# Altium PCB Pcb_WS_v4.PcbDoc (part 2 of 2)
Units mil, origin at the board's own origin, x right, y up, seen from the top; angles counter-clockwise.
Board outline 3890 x 3890 mil, 2 copper layers (Top Layer, Bottom Layer); 77 components, 63 nets, 250 pads, 399 vias.
Unrouted connection lines stored in the file: 3.
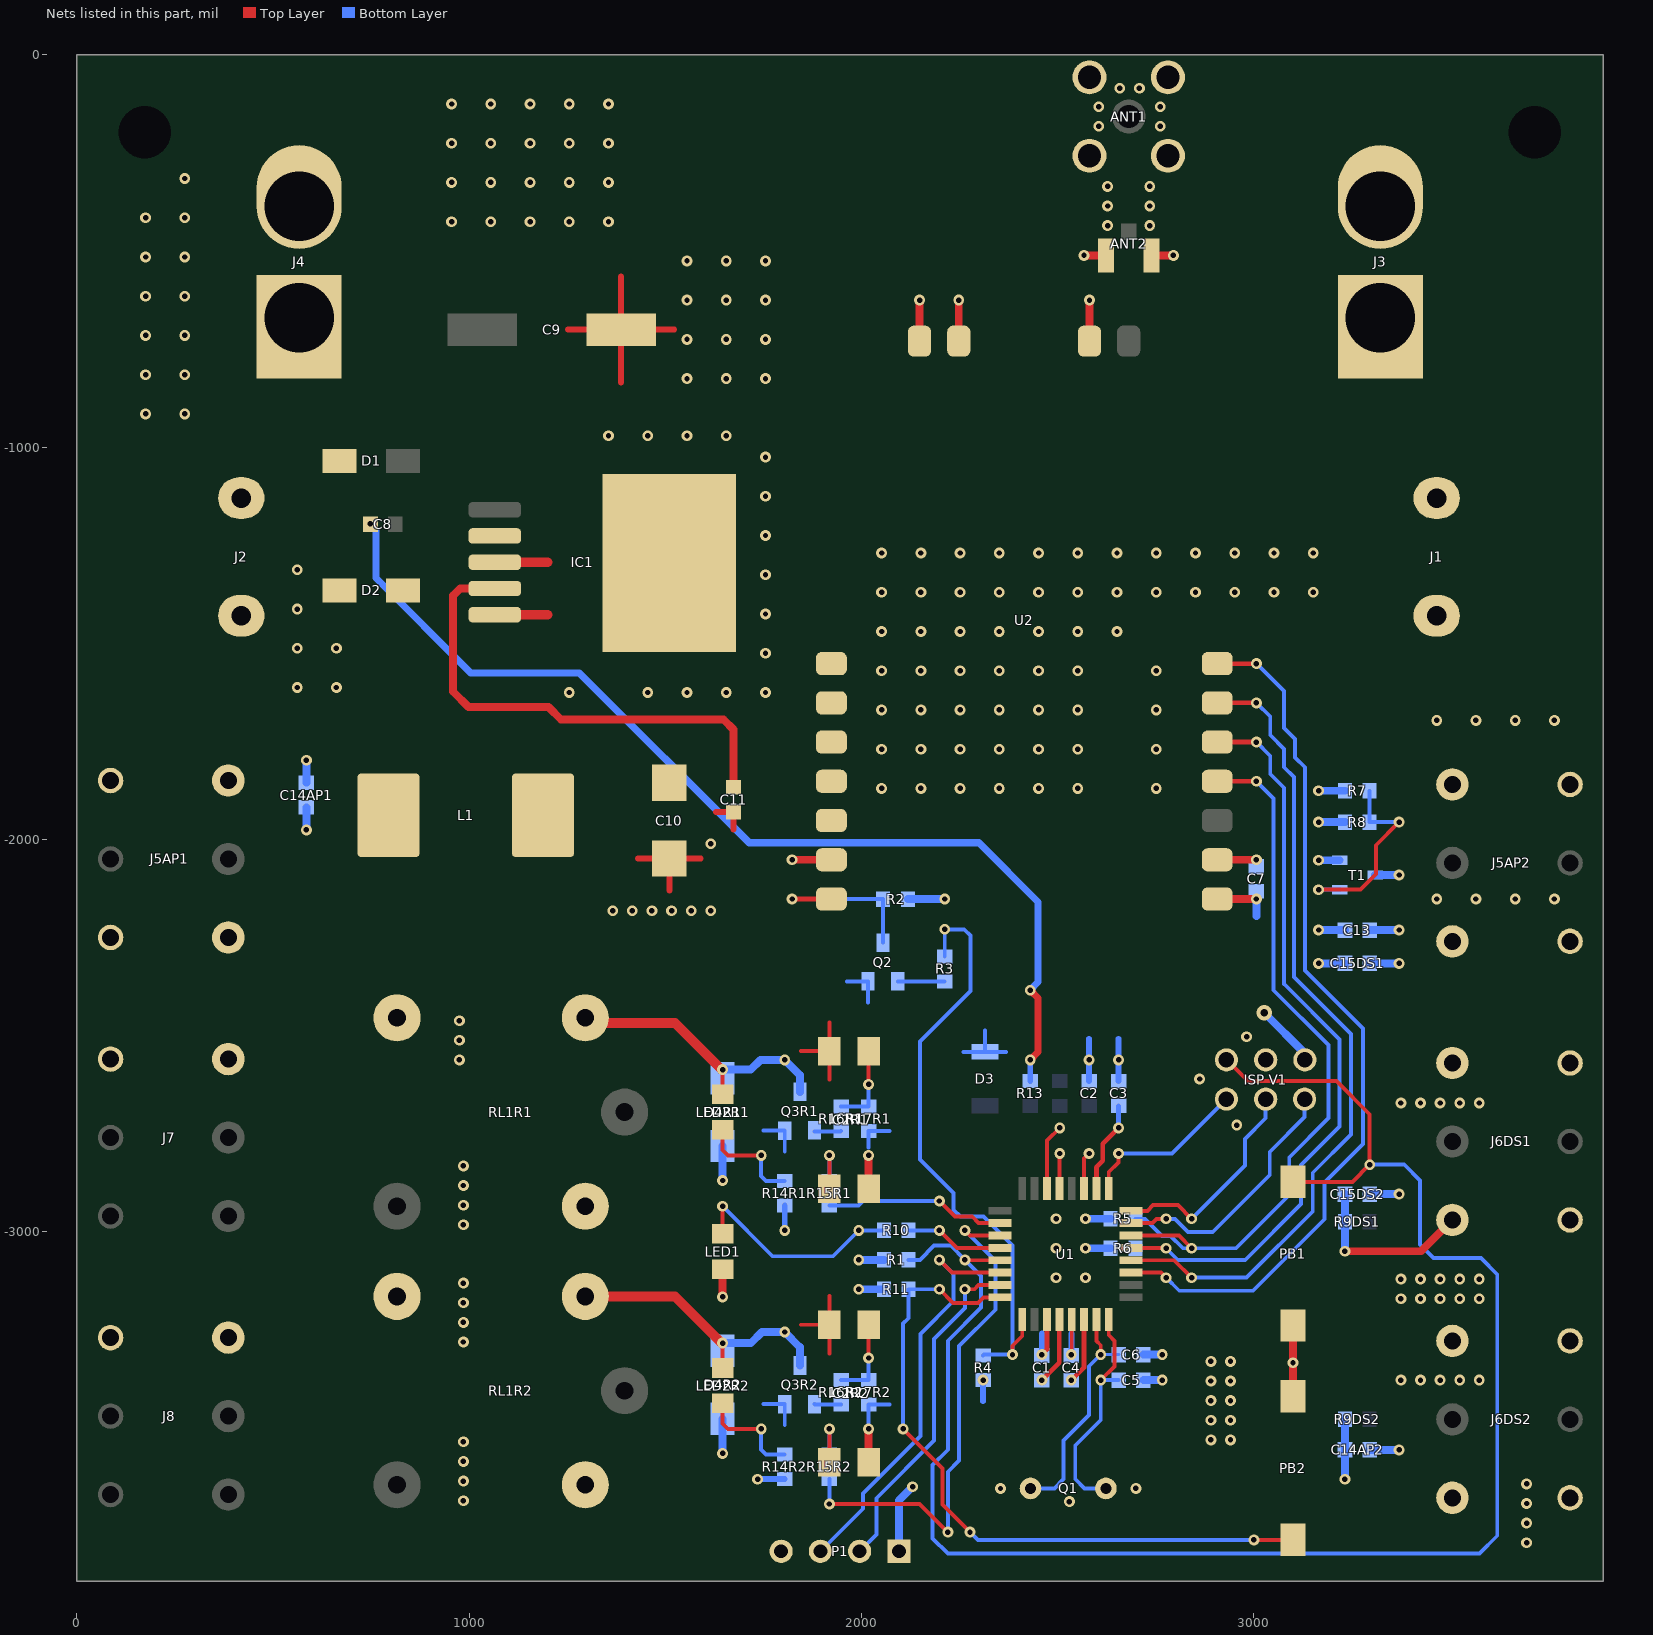
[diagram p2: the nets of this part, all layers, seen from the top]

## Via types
v1: diameter 27.56, hole 13.78, Top Layer to Bottom Layer, tented both sides, 320 vias
v2: diameter 20, hole 11.81, Top Layer to Bottom Layer, tented both sides, 76 vias
v3: diameter 27.56, hole 13.78, Top Layer to Bottom Layer, tented top, 2 vias
v4: diameter 39.37, hole 19.68, Top Layer to Bottom Layer, tented both sides, 1 vias

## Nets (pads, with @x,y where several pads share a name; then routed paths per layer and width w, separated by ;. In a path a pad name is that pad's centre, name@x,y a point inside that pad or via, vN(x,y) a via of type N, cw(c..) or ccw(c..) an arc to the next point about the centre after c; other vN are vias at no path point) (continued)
GND: "ISP V1.5" C1.2 C2.1 C3.2 C4.2 C5.2 C6.2 C7.2 C8.2 C9.2 C10.2 C11.2 C13.2 C14AP1.1 C14AP2.1 C15DS1.1 C15DS2.1 D2.2 D3.2 IC1.3 IC1.5 IC1.6 IC2R1.2 IC2R2.2 J2.1 J4.1 J5AP1.3 J5AP2.3 J6DS1.3 J6DS2.3 LED1.2 P1.4 PB1.2 PB2.2 Q2.2 Q3R1.2 Q3R2.2 R4.1 R5.2 R6.2 R7.1 R13.2 R17R1.1 R17R2.1 U1.3 U1.5 U1.21 U2.7 U2.9 | length 6440.5
  Top Layer w9.84: U1.21@2504.06,-2889.41 2504.06,-2800.94 v1(2505,-2800) ; v1(2534.61,-3312.82) 2535.55,-3311.87 U1.5@2535.55,-3223.41
  Top Layer w12: v1(2459.61,-3312.82) 2472.56,-3299.87 U1.3@2472.56,-3223.41
  Top Layer w15: 1251.94,-700 C9.2@1387.17,-700 ; 1387.17,-835.23 C9.2@1387.17,-700 ; 1387.17,-564.77 C9.2@1387.17,-700 ; 1430,-2047.96 C10.2@1510,-2047.96 1590,-2047.96 ; 1510.45,-2130.07 C10.2@1510.45,-2050.07 ; 1522.4,-700 C9.2@1387.17,-700 ; 1629.05,-1929.5 C11.2@1673.55,-1929.5 1673.55,-1974
  Top Layer w18: v1(2430,-2561.61) 2450,-2541.61 2450,-2512.31 2450,-2404 v1(2430,-2384)
  Top Layer w20: v1(1645.86,-3165.54) LED1.2@1645.86,-3095 ; v1(1822.96,-2051.51) U2.9@1922.96,-2051.51 ; IC2R2.2@2017.86,-3586.94 v1(2017.86,-3502.13) ; IC2R1.2@2017.86,-2889.66 v1(2017.86,-2804.85) ; U2.7@2906.43,-2151.51 v3(3006.43,-2151.51) ; PB2.2@3099.53,-3418.86 v1(3099.53,-3333.37) PB1.2@3099.53,-3238.46
  Top Layer w25: IC1.5@1065.04,-1426.9 1200.27,-1426.9 ; IC1.3@1065.04,-1293.04 1200.27,-1293.04
  Bottom Layer w10: 1750.16,-3438.9 Q3R2.2@1804.06,-3438.9 1804.06,-3492.8 ; 1750.16,-2741.62 Q3R1.2@1804.06,-2741.62 1804.06,-2795.52 ; 1962.5,-2361.42 Q2.2@2016.4,-2361.42 2016.4,-2415.32 ; v1(2017.86,-3502.13) R17R2.1@2017.86,-3440.26 2071.76,-3440.26 ; 2017.86,-2784.35 R17R1.1@2017.86,-2742.98 2071.76,-2742.98 ; 2260.17,-2540.88 D3.2@2314.07,-2540.88 ; 2314.07,-2486.98 D3.2@2314.07,-2540.88 ; 2367.98,-2540.88 D3.2@2314.07,-2540.88
  Bottom Layer w15: 2309.61,-3431.72 v1(2309.61,-3377.82) ; R13.2@2430,-2615.69 v1(2430,-2561.61) ; v1(2459.61,-3312.82) 2459.61,-3258.92 ; v1(2534.61,-3312.82) 2534.61,-3258.92 ; C2.1@2580,-2615.69 v1(2580,-2561.61) 2580,-2507.53 ; C3.2@2655,-2615.69 v1(2655,-2561.61) 2655,-2507.53
  Bottom Layer w18: v1(748,-1195.22) 748,-1196.54 762,-1210.54 762,-1333.26 1003.74,-1575 1280.5,-1575 1713.5,-2008 2299.34,-2008 2450,-2158.67 2450,-2363.3 2430,-2383.3 v1(2430,-2384)
  Bottom Layer w20: C14AP1.1@585,-1855 v1(585,-1797.68) ; v1(2570.81,-3041.61) R6.2@2634.67,-3041.61 ; v1(2570.81,-2966.61) R5.2@2634.67,-2966.61 ; C5.2@2718.3,-3377.82 v1(2766.21,-3377.82) ; C6.2@2718.3,-3312.82 v1(2766.21,-3312.82) ; 3006.43,-2195 v3(3006.43,-2151.51) ; v1(3165,-2315.54) C15DS1.1@3232.01,-2315.54 ; v1(3165,-2230.54) C13.2@3232.01,-2230.54 ; v1(3165,-1875.54) R7.1@3232.01,-1875.54 ; C14AP2.1@3295,-3555.54 v1(3370,-3555.54) ; C15DS2.1@3295,-2903.69 v1(3370,-2903.69)
  other v1: 2529.75,-3687.48 985,-3685 2353.96,-3654.09 2699.14,-3653.67 985,-3635 985,-3585 985,-3535 2890.32,-3529.98 2940.32,-3529.98 2890.32,-3479.98 2940.32,-3479.98 2890.32,-3429.98 2940.32,-3429.98 2890.32,-3379.98 2940.32,-3379.98 3374.51,-3377.82 3424.51,-3377.82 3474.51,-3377.82 3524.51,-3377.82 3574.51,-3377.82 2890.32,-3329.98 2940.32,-3329.98 985,-3280.49 985,-3230.49 985,-3180.49 3374.51,-3170.39 3424.51,-3170.39 3474.51,-3170.39 3524.51,-3170.39 3574.51,-3170.39 985,-3130.49 3374.51,-3120.39 3424.51,-3120.39 3474.51,-3120.39 3524.51,-3120.39 3574.51,-3120.39 2495.81,-3116.61 2570.81,-3116.61 2495.81,-3041.61 985,-2981.79 2495.81,-2966.61 985,-2931.79 985,-2881.79 985,-2831.79 2956.35,-2727.67 3374.51,-2671.35 3424.51,-2671.35 3474.51,-2671.35 3524.51,-2671.35 3574.51,-2671.35 2861.6,-2610.31 975,-2561.61 975,-2511.61 2981.3,-2502.57 975,-2461.61 1365.62,-2181.28 1415.62,-2181.28 1465.62,-2181.28 1515.62,-2181.28 1565.62,-2181.28 1615.62,-2181.28 3465.86,-2151.51 3565.86,-2151.51 3665.86,-2151.51 3765.86,-2151.51 1615.62,-2010.75 2051.06,-1869.52 2151.06,-1869.52 2251.06,-1869.52 2351.06,-1869.52 2451.06,-1869.52 2551.06,-1869.52 2751.06,-1869.52 2051.06,-1769.52 2151.06,-1769.52 2251.06,-1769.52 2351.06,-1769.52 2451.06,-1769.52 2551.06,-1769.52 2751.06,-1769.52 3465.86,-1696.29 3565.86,-1696.29 3665.86,-1696.29 3765.86,-1696.29 2051.06,-1669.52 2151.06,-1669.52 2251.06,-1669.52 2351.06,-1669.52 2451.06,-1669.52 2551.06,-1669.52 2751.06,-1669.52 1255,-1625 1455,-1625 1555,-1625 1655,-1625 1755,-1625 561.41,-1612.43 661.41,-1612.43 2051.06,-1569.52 2151.06,-1569.52 2251.06,-1569.52 2351.06,-1569.52 2451.06,-1569.52 2551.06,-1569.52 2751.06,-1569.52 1755,-1525 561.41,-1512.43 661.41,-1512.43 2051.06,-1469.52 2151.06,-1469.52 2251.06,-1469.52 2351.06,-1469.52 2451.06,-1469.52 2551.06,-1469.52 2651.06,-1469.52 1755,-1425 561.41,-1412.43 2051.06,-1369.52 2151.06,-1369.52 2251.06,-1369.52 2351.06,-1369.52 2451.06,-1369.52 2551.06,-1369.52 2651.06,-1369.52 2751.06,-1369.52 2851.06,-1369.52 2951.06,-1369.52 3051.06,-1369.52 3151.06,-1369.52 1755,-1325 561.41,-1312.43 2051.06,-1269.52 2151.06,-1269.52 2251.06,-1269.52 2351.06,-1269.52 2451.06,-1269.52 2551.06,-1269.52 2651.06,-1269.52 2751.06,-1269.52 2851.06,-1269.52 2951.06,-1269.52 3051.06,-1269.52 3151.06,-1269.52 1755,-1225 1755,-1125 1755,-1025 1355,-970.49 1455,-970.49 1555,-970.49 1655,-970.49 175,-915 275,-915 1555,-825 1655,-825 1755,-825 175,-815 275,-815 1555,-725 1655,-725 1755,-725 175,-715 275,-715 1555,-625 1655,-625 1755,-625 175,-615 275,-615 1555,-525 1655,-525 1755,-525 175,-515 275,-515 955,-425 1055,-425 1155,-425 1255,-425 1355,-425 175,-415 275,-415 955,-325 1055,-325 1155,-325 1255,-325 1355,-325 275,-315 955,-225 1055,-225 1155,-225 1255,-225 1355,-225 955,-125 1055,-125 1155,-125 1255,-125 1355,-125
GND-SOLAR: J1.2 J3.1
GND_ANT: ANT1.2 ANT2.2 U2.15 U2.16 U2.17 | length 425.1
  Top Layer w20: U2.15@2147.76,-729.46 v1(2147.76,-625) ; U2.16@2247.76,-729.46 v1(2247.76,-625) ; v1(2566.92,-511) ANT2.2@2622.76,-511 ; U2.17@2580.84,-729.46 v1(2580.84,-625) ; ANT2.2@2738.91,-511 v1(2794.75,-511)
  other v1: 2627.07,-435 2734.27,-435 2627.07,-385 2734.27,-385 2627.07,-335 2734.27,-335 2604.38,-181.91 2761.22,-181.91 2604.38,-131.91 2761.22,-131.91 2658.24,-85.19 2708.24,-85.19
LED: R10.1 U1.28 | length 251.5
  Top Layer w10: v1(2198.39,-2996.21) 2242.84,-3040.66 U1.28@2352.8,-3040.66
  Bottom Layer w10: R10.1@2119.71,-2996.21 v1(2198.39,-2996.21)
M0: U1.11 U2.1 | length 2257
  Top Layer w10: U1.11@2686.8,-3103.65 2763.26,-3103.65 v1(2776.21,-3116.61)
  Top Layer w12: U2.1@2906.43,-1551.51 v1(3006.43,-1551.51)
  Bottom Layer w10: v1(2776.21,-3116.61) 2809.61,-3150 2997.76,-3150 3180,-2967.76 3180,-2873.56 3277.78,-2775.78 3277.78,-2481.78 3130,-2334 3130,-1815.68 3104.99,-1790.67 3104.99,-1743.7 3076.66,-1715.38 3076.66,-1621.74 v1(3006.43,-1551.51)
M1: U1.12 U2.2 | length 2088.2
  Top Layer w10: U1.12@2686.8,-3072.16 2796.76,-3072.16 v1(2841.21,-3116.61)
  Top Layer w12: U2.2@2906.43,-1651.51 v1(3006.43,-1651.51)
  Bottom Layer w10: v1(2841.21,-3116.61) 2981.3,-3116.61 3150,-2947.91 3150,-2849.22 3247.63,-2751.6 3247.63,-2495.7 3101.84,-2349.92 3101.84,-1840.85 3076.66,-1815.68 3076.66,-1768.71 3041.54,-1733.59 3041.54,-1686.63 v1(3006.43,-1651.51)
MISO: "ISP V1.2" U1.16 | length 558.1
  Top Layer w10: U1.16@2686.8,-2946.17 2728.65,-2946.17 2743.21,-2931.61 2806.21,-2931.61 v1(2841.21,-2966.61)
  Bottom Layer w10: v1(2841.21,-2966.61) 2976.74,-2831.08 2976.74,-2763.58 3030,-2710.32 3030,-2661.61
MOSI: "ISP V1.3" U1.15 | length 662
  Top Layer w10: U1.15@2686.8,-2977.67 2741.13,-2977.67 2752.19,-2966.61 v1(2776.21,-2966.61)
  Bottom Layer w10: v1(2776.21,-2966.61) 2798.31,-2966.61 2831.71,-3000 2895.12,-3000 3040.32,-2854.81 3040.32,-2795.88 3129,-2707.19 3129,-2661.61
NetD2_1: D2.1 IC1.2 L1.1
NetD4R1_2: D4R1.2 LED2R1.2 Q3R1.3 RL1R1.4 | length 728.5
  Top Layer w10: LED2R1.2@1645.86,-2649.46 v1(1645.86,-2586.19)
  Top Layer w25: RL1R1.4@1295.86,-2467.18 1524.46,-2467.18 v1@1643.47,-2586.19
  Bottom Layer w20: D4R1.2@1643.47,-2586.19 v1(1645.86,-2586.19) 1717.53,-2586.19 1742.12,-2561.61 v1(1804.06,-2561.61) 1842.66,-2600.2 Q3R1.3@1842.66,-2643.2
NetD4R2_2: D4R2.2 LED2R2.2 Q3R2.3 RL1R2.4 | length 734
  Top Layer w10: LED2R2.2@1645.86,-3346.74 v1(1645.86,-3283.47)
  Top Layer w25: RL1R2.4@1295.86,-3164.46 1524.46,-3164.46 v1@1643.47,-3283.47
  Bottom Layer w20: D4R2.2@1643.47,-3283.47 1717.53,-3283.47 1746,-3255 v1(1804.06,-3255) 1842.66,-3293.6 Q3R2.3@1842.66,-3340.48
NetIC2R1_1: IC2R1.1 R15R1.2 | length 149.9
  Top Layer w10: IC2R1.1@1917.86,-2889.66 v1(1917.86,-2804.85)
  Bottom Layer w10: R15R1.2@1917.86,-2869.99 v1(1917.86,-2804.85)
NetIC2R2_1: IC2R2.1 R15R2.2 | length 149.9
  Top Layer w10: IC2R2.1@1917.86,-3586.94 v1(1917.86,-3502.13)
  Bottom Layer w10: R15R2.2@1917.86,-3567.27 v1(1917.86,-3502.13)
NetLED1_1: LED1.1 R10.2 | length 561.5
  Top Layer w10: LED1.1@1645.86,-3005 v1(1645.86,-2934.46)
  Bottom Layer w10: v1(1645.86,-2934.46) 1773.4,-3062 1927.07,-3062 v1(1992.86,-2996.21) R10.2@2056.72,-2996.21
NetLED2R1_1: LED2R1.1 R14R1.2 | length 273.2
  Top Layer w10: LED2R1.1@1645.86,-2739.46 1645.86,-2790.86 1659.86,-2804.85 v1(1744.06,-2804.85)
  Bottom Layer w10: v1(1744.06,-2804.85) 1744.06,-2857.4 1756.65,-2869.99 R14R1.2@1804.06,-2869.99
NetLED2R2_1: LED2R2.1 R14R2.2 | length 273.2
  Top Layer w10: LED2R2.1@1645.86,-3436.74 1645.86,-3488.14 1659.86,-3502.13 v1(1744.06,-3502.13)
  Bottom Layer w10: v1(1744.06,-3502.13) 1744.06,-3554.68 1756.65,-3567.27 R14R2.2@1804.06,-3567.27
NetQ2_1: Q2.1 R3.2 | length 119.9
  Bottom Layer w10: Q2.1@2092.2,-2361.2 R3.2@2212.06,-2361.2
NetQ3R1_1: Q3R1.1 R16R1.2 | length 68.4
  Bottom Layer w10: Q3R1.1@1879.86,-2743.99 1946.85,-2743.99 R16R1.2@1947.86,-2742.98
NetQ3R2_1: Q3R2.1 R16R2.2 | length 68.7
  Bottom Layer w10: Q3R2.1@1879.86,-3438.69 1881.43,-3440.26 R16R2.2@1947.86,-3440.26
NetR7_2: R7.2 R8.2 T1.1 | length 527.4
  Top Layer w10: v1(3165,-2127.67) 3271.14,-2127.67 3311.13,-2087.68 3311.13,-2014.41 v1(3370,-1955.54)
  Bottom Layer w10: v1(3165,-2127.67) T1.1@3218.23,-2127.67 ; R7.2@3295,-1875.54 R8.2@3295,-1955.54 v1(3370,-1955.54)
NetU1_19: U1.19 | length 94.8
  Top Layer w10: U1.19@2567.05,-2889.41 2567.05,-2812.95 v1(2580,-2800)
NetU1_22: U1.22 | length 167.8
  Top Layer w10: U1.22@2472.56,-2889.41 2472.56,-2767.44 v1(2505,-2735)
NetU2_10: U2.10
NetU2_11: U2.11
NetU2_12: U2.12
NetU2_13: U2.13
NetU2_14: U2.14
OPEN1: J7.1 RL1R1.3
OPEN2: J8.1 RL1R2.3
P5V-Main: "ISP V1.6" C1.1 C3.1 C4.1 C7.1 C10.1 C11.1 D4R1.1 D4R2.1 IC1.4 IC2R1.4 IC2R2.4 L1.2 P1.1 R1.1 R2.2 R8.1 R11.1 R14R1.1 R14R2.1 RL1R1.5 RL1R2.5 T1.2 U1.4 U1.6 U1.18 U2.6 | length 3364.2
  Top Layer w10: 1845,-3236.54 IC2R2.4@1917.86,-3236.54 ; 1845,-2539.26 IC2R1.4@1917.86,-2539.26 ; 1917.86,-3309.4 IC2R2.4@1917.86,-3236.54 ; 1917.86,-3163.68 IC2R2.4@1917.86,-3236.54 ; 1917.86,-2612.12 IC2R1.4@1917.86,-2539.26 ; 1917.86,-2466.41 IC2R1.4@1917.86,-2539.26
  Top Layer w12: v1(2459.61,-3377.82) 2504.06,-3333.37 U1.4@2504.06,-3223.41 ; v1(2534.61,-3377.82) 2567.05,-3345.38 U1.6@2567.05,-3223.41 ; U1.18@2598.54,-2889.41 2598.54,-2835.08 2615,-2818.62 2615,-2775 v1(2655,-2735)
  Top Layer w20: IC1.4@1065.04,-1359.97 977.03,-1359.97 959,-1378 959,-1622.98 998.02,-1662 1202,-1662 1234.23,-1694.23 1648.39,-1694.23 1673.55,-1719.39 C11.1@1673.55,-1866.5 ; U2.6@2906.43,-2051.51 v3(3006.43,-2051.51)
  Bottom Layer w12: v1(2655,-2735) C3.1@2655,-2678.68
  Bottom Layer w15: v1(1735,-3630.26) R14R2.1@1804.06,-3630.26 ; v1(1804.06,-2996.21) R14R1.1@1804.06,-2932.98
  Bottom Layer w20: v1(1645.86,-3564.53) D4R2.1@1645.86,-3476.61 ; v1(1645.86,-2868.99) D4R1.1@1645.86,-2781.07 ; v1(1992.86,-3146.21) R11.1@2056.72,-3146.21 ; v1(1992.86,-3071.21) R1.1@2056.72,-3071.21 ; P1.1@2095,-3814 2095,-3684.45 v1(2130,-3649.45) ; R2.2@2117.99,-2151.51 v1(2212.06,-2151.51) ; v4(3026.21,-2441.61) 3130,-2545.4 3130,-2561.61 ; v1(3165,-2052.86) T1.2@3218.23,-2052.86 ; v1(3165,-1955.54) R8.1@3232.01,-1955.54
P5V-SEN: C13.1 C14AP1.2 C14AP2.2 C15DS1.2 C15DS2.2 J5AP1.1 J5AP2.1 J6DS1.1 J6DS2.1 R9DS1.2 R9DS2.2 T1.3 | length 873.8
  Top Layer w20: v1(3232.01,-3049.23) 3426.09,-3049.23 J6DS1.1@3505.86,-2969.46
  Bottom Layer w20: v1(585,-1975.31) C14AP1.2@585,-1917.99 ; v1(3232.01,-3630.54) C14AP2.2@3232.01,-3555.54 R9DS2.2@3232.01,-3477.74 ; v1(3232.01,-3049.23) R9DS1.2@3232.01,-2974.23 C15DS2.2@3232.01,-2903.69 ; C15DS1.2@3295,-2315.54 v1(3370,-2315.54) ; C13.1@3295,-2230.54 v1(3370,-2230.54) ; T1.3@3308.78,-2090.26 v1(3370,-2090.26)
  other v1: 3695,-3792.26 3695,-3742.26 3695,-3692.26 3695,-3642.26
P12V-BAT: D1.2 J2.2 J4.2
P16V-SOLAR: J1.1 J3.2
RESET-E32: R3.1 R4.2 U1.1 | length 1571.2
  Top Layer w10: v1(2384.61,-3312.82) 2384.61,-3290.21 2409.57,-3265.25 U1.1@2409.57,-3223.41
  Bottom Layer w9.84: R3.1@2212.06,-2298.21 v1(2212.06,-2228.74)
  Bottom Layer w10: v1(2212.06,-2228.74) 2261.59,-2228.74 2277.53,-2244.68 2277.53,-2386.25 2148.79,-2514.99 2148.79,-2815.03 2234.61,-2900.85 2234.61,-2944.23 2251.6,-2961.21 2311.16,-2961.21 2384.61,-3034.66 v1(2384.61,-3312.82) 2311.61,-3312.82 R4.2@2309.61,-3314.83
RL-CT-QR1: IC2R1.3 R16R1.1 R17R1.2 | length 210.7
  Top Layer w10: v1(2017.86,-2624.07) IC2R1.3@2017.86,-2539.26
  Bottom Layer w10: R16R1.1@1947.86,-2679.99 R17R1.2@2017.86,-2679.99 v1(2017.86,-2624.07)
RL-CT-QR2: IC2R2.3 R16R2.1 R17R2.2 | length 210.7
  Top Layer w10: v1(2017.86,-3321.35) IC2R2.3@2017.86,-3236.54
  Bottom Layer w10: R16R2.1@1947.86,-3377.27 R17R2.2@2017.86,-3377.27 v1(2017.86,-3321.35)
RL-CTL1: R15R1.1 U1.26 | length 463.2
  Top Layer w10: v1(2198.39,-2921.21) 2238.39,-2961.21 2282.02,-2961.21 2298.48,-2977.67 U1.26@2352.8,-2977.67
  Bottom Layer w10: R15R1.1@1917.86,-2932.98 1991.67,-2932.98 2003.44,-2921.21 v1(2198.39,-2921.21)
RL-CTL2: R15R2.1 U1.27 | length 1341.3
  Top Layer w10: v1(1917.86,-3693.49) 2147.09,-3693.49 2218.6,-3765 v1(2220,-3765) ; v1(2263.39,-2996.21) 2276.35,-3009.17 U1.27@2352.8,-3009.17
  Bottom Layer w10: v1(1917.86,-3693.49) R15R2.1@1917.86,-3630.26 ; v1(2220,-3765) 2220,-3611.2 2248.78,-3582.42 2248.78,-3291.22 2341.63,-3198.37 2341.63,-3074.45 v1(2263.39,-2996.21)
RST-E32: Q2.3 R2.1 U2.8 | length 443.5
  Top Layer w12: v1(1822.96,-2151.51) U2.8@1922.96,-2151.51
  Bottom Layer w10: v1(1822.96,-2151.51) R2.1@2055,-2151.51 Q2.3@2055,-2262.99
RST_MCU: "ISP V1.4" PB1.1 R1.2 U1.29 | length 4483.3
  Top Layer w10: v1(2263.39,-3071.21) 2264.34,-3072.16 U1.29@2352.8,-3072.16 ; 2930,-2561.61 2931.61,-2561.61 2985,-2615 3210,-2615 3295,-2700 v1(3295,-2828.69) 3251.37,-2872.31 PB1.1@3099.53,-2872.31
  Bottom Layer w10: R1.2@2119.71,-3071.21 2148.79,-3071.21 2185,-3035 2227.18,-3035 v1(2263.39,-3071.21) 2304.79,-3112.61 2304.79,-3192.6 2220,-3277.39 2220,-3555.29 2180.91,-3594.38 2180.91,-3780.91 2220,-3820 3574.61,-3820 3620.18,-3774.43 3620.18,-3108.18 3578.32,-3066.32 3457.64,-3066.32 3423.54,-3032.22 3423.54,-2869 3383.23,-2828.69 v1(3295,-2828.69)
RXD-E32: R6.1 U1.13 U2.3 | length 1989.3
  Top Layer w10: U1.13@2686.8,-3040.66 2775.27,-3040.66 v1(2776.21,-3041.61)
  Top Layer w12: U2.3@2906.43,-1751.51 v1(3006.43,-1751.51)
  Bottom Layer w10: R6.1@2697.66,-3041.61 v1(2776.21,-3041.61) 2805.82,-3071.21 2977.86,-3071.21 3120,-2929.08 3120,-2829.46 3218.23,-2731.23 3218.23,-2509.12 3076.66,-2367.55 3076.66,-1867.89 3041.54,-1832.78 3041.54,-1786.63 v1(3006.43,-1751.51)
RXM: P1.3 U1.30 | length 1066.3
  Top Layer w10: v1(2198.39,-3071.21) 2230.84,-3103.65 U1.30@2352.8,-3103.65
  Bottom Layer w10: P1.3@1895,-3814 2003.44,-3705.56 2003.44,-3666.56 2150,-3520 2150,-3260 2234.61,-3175.39 2234.61,-3107.43 v1(2198.39,-3071.21)
SCK: "ISP V1.1" U1.17 | length 432.1
  Top Layer w10: U1.17@2630.04,-2889.41 2630.04,-2847.57 2655,-2822.61 v1(2655,-2800)
  Bottom Layer w10: v1(2655,-2800) 2791.61,-2800 2930,-2661.61
TXD-E32: R5.1 U1.14 U2.4 | length 1919.5
  Top Layer w10: U1.14@2686.8,-3009.17 2808.77,-3009.17 v1(2841.21,-3041.61)
  Top Layer w12: U2.4@2906.43,-1851.51 v1(3006.43,-1851.51)
  Bottom Layer w10: R5.1@2697.66,-2966.61 2722.59,-2966.61 2765.98,-3010 2787.28,-3010 2818.89,-3041.61 v1(2841.21,-3041.61) 2954.61,-3041.61 3090,-2906.21 3090,-2810 3190,-2710 3190,-2524 3050,-2384 3050,-1895.08 v1(3006.43,-1851.51)
TXM: P1.2 U1.31 | length 873
  Top Layer w10: v1(2263.39,-3146.21) 2287.41,-3146.21 2298.48,-3135.15 U1.31@2352.8,-3135.15
  Bottom Layer w10: P1.2@1995,-3814 2038.25,-3770.75 2038.25,-3678.8 2185,-3532.05 2185,-3272.5 2263.39,-3194.11 v1(2263.39,-3146.21)
WAKE: PB2.1 R11.2 U1.32 | length 1780.3
  Top Layer w10: v1(2105.83,-3502.13) 2206.2,-3602.5 2206.2,-3694.85 v1(2276.35,-3765) ; v1(2198.39,-3146.21) 2233.39,-3181.21 2296.39,-3181.21 2310.96,-3166.65 U1.32@2352.8,-3166.65 ; v1(3000,-3785) PB2.1@3099.53,-3785
  Bottom Layer w10: v1(2105.83,-3502.13) 2105.83,-3233.88 2119.71,-3220 R11.2@2119.71,-3146.21 v1(2198.39,-3146.21) ; v1(2276.35,-3765) 2296.35,-3785 v1(3000,-3785)
XTAL1: C6.1 Q1.1 U1.7 | length 590.6
  Top Layer w10: U1.7@2598.54,-3223.41 2598.54,-3277.74 2609.61,-3288.8 v1(2609.61,-3312.82)
  Bottom Layer w8: v1(2609.61,-3312.82) C6.1@2655.31,-3312.82
  Bottom Layer w10: Q1.1@2430.49,-3653.88 2491.32,-3653.88 2514.95,-3630.26 2514.95,-3531.96 2580,-3466.91 2580,-3342.43 v1(2609.61,-3312.82)
XTAL2: C5.1 Q1.2 U1.8 | length 587.9
  Top Layer w10: v1(2609.61,-3377.82) 2644.61,-3342.82 2644.61,-3277.74 2630.04,-3263.17 U1.8@2630.04,-3223.41
  Bottom Layer w10: Q1.2@2622.61,-3653.88 2568.17,-3653.88 2544.55,-3630.26 2544.55,-3544.23 2609.61,-3479.17 v1(2609.61,-3377.82) C5.1@2655.31,-3377.82
pads on no net: HOLE.1

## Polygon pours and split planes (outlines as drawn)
P5V-Main on Top Layer "P5V-MAIN_L01_P035" (solid, pour order 35): 1730.29,-1935.15 1730.29,-1770 1842.96,-1770 1842.96,-1914.11 1864,-1935.15 3191.79,-1935.15 3191.79,-2077 3101.84,-2077 3101.84,-2469.05 2824.07,-2469.05 2824.07,-2758.37 2930,-2758.37 2930,-3269.94 2736.81,-3269.94 2736.81,-3570 2657.31,-3570 2430.49,-3570 2430.49,-3713.56 1187.95,-3713.56 1187.95,-2290 1320,-2290 1320,-2240 1659.86,-2240 1659.86,-1990 1715,-1990 1715,-1935.15
GND on Top Layer "GND_L01_P027" (solid, remove dead copper, pour order 27): 1715,-1990 1715,-1898 1850,-1898 1850,-1215 1900,-1215 1900,-35 35,-35 35,-1640 650,-1640 650,-2240 1650,-2240 1650,-1990
GND on Top Layer "GND_L01_P040" (solid, pour order 40): 795,-2593.37 925,-2723.37 925,-2895.38 925,-3855 1055,-3855 1055,-2395 564.28,-2395 485.95,-2313.75 485.95,-2135 35,-2135 35,-2461.61 533.23,-2461.61 665,-2593.37
GND on Top Layer "GND_L01_P039" (solid, pour order 39): 2931.03,-3269.94 2737.18,-3269.94 2737.18,-3570 2985,-3570 3855,-3570 3855,-1651.51 3200,-1651.51 3200,-1215 2000,-1215 2000,-1922 3191.79,-1922 3191.79,-2077 3101.84,-2077 3101.84,-2469.05 2841.21,-2469.05 2841.21,-2758.37 2931.03,-2758.37
P5V-SEN on Top Layer "P5V-SEN_L01_P031" (solid, remove dead copper, pour order 31): 2622.61,-3597.24 2622.61,-3740 2175,-3740 2148.56,-3713.56 1187.95,-3713.56 1187.95,-2290 615.98,-2290 615.98,-1780 590.99,-1755 80,-1755 40,-1795 40,-1917.51 60.49,-1938 448.78,-1938 484.78,-1974 484.78,-2312.88 566.9,-2395 985,-2395 1055,-2465 1055,-3829.51 2146.6,-3829.51 2172.09,-3855 2975,-3855 2975,-3729.52 3020.48,-3729.52 3164.52,-3729.52 3164.52,-3855 3290,-3855 3855,-3855 3855,-3597.24
GND_ANT on Top Layer "GND_ANT_L01_P037" (solid, pour order 37): 2000,-60.49 2000,-1115 3025,-1115 3025,-60.49
GND-SOLAR on Top Layer "GND-SOLAR_L01_P028" (solid, remove dead copper, pour order 28): 3300,-1115 3125,-1115 3125,-35 3855,-35 3855,-1580 3300,-1580
no net on Top Layer "Top Layer-No Net" (solid, shelved, pour order 14): 1060.77,1094.95
no net on Top Layer "AutoNaming" (solid, shelved, pour order 22): -29.14,-3739.46
no net on Top Layer "AutoNaming" (solid, shelved, pour order 26): -29.14,-3739.46
GND on Bottom Layer "GND-Bottom" (solid, remove dead copper, pour order 38): 3432.98,-2059.46 3432.98,-2180 3855,-2180 3855,-1650 3200,-1650 3200,-1215 1900,-1215 1900,-35 35,-35 35,-3855 3630,-3855 3630,-2463 3365.37,-2463 3365.37,-2059.46
P5V-SEN on Bottom Layer "P5V-SEN_L02_P030" (solid, remove dead copper, pour order 30): 3365.37,-2450.49 3377.88,-2463 3610.35,-2463 3630,-2482.65 3630,-3553.18 3630,-3855 3845,-3855 3845,-2210 3830,-2195 3432.69,-2195 3417.69,-2180 3417.69,-2059.46 3365.37,-2059.46
GND_ANT on Bottom Layer "GND_ANT_L02_P033" (solid, pour order 33): 2000,-60.49 2000,-1115 3025,-1115 3025,-60.49
P16V-SOLAR on Bottom Layer "P16V-SOLAR_L02_P029" (solid, pour order 29): 3300,-1115 3125,-1115 3125,-27.5 3862.5,-27.5 3862.5,-1580 3300,-1580

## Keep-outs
Bottom Layer:
  region: 3864.91,-1648.04
Keep-Out Layer:
  the board outline again, w5

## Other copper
Top Layer:
  region net EARTH: 15,-3875 3875,-3875.18 3875,-14.96 2890,-15 2890,-35 3855,-35 3855,-3855 35,-3855 35,-35 2480,-35 2480,-15 15,-15
  pour cut-out: 2999,-2021.73 cw(c2999,-2029.16) 3006.43,-2029.16 3006.43,-2075.16 cw(c3000.3,-2075.16) 3000.3,-2081.28 2866.81,-2081.28 2866.81,-2021.73
  pour cut-out: 2515,-3398 ccw(c2515,-3389) 2524,-3389 2524,-3378 2545,-3378 2545,-3389 ccw(c2554,-3389) 2554,-3398 2609.61,-3398 2609.61,-3312.82 2370.19,-3312.82 2370.19,-3392 2384,-3392 2384,-3398 2441,-3398 ccw(c2441,-3390) 2449,-3390 2449,-3378 2470,-3378 2470,-3390 ccw(c2478,-3390) 2478,-3398
  pour cut-out: 2632.42,-2714.61 cw(c2632.42,-2724.19) 2642,-2724.19 2642,-2735 ccw(c2655,-2735) 2655,-2748 2667,-2748 cw(c2667.2,-2756.2) 2675.39,-2756 2675.39,-2800 2430,-2800 2430,-2714.61
  pour cut-out: 3065.36,-3375.4 3133,-3375.4 3133,-3462.4 3065.36,-3462.4
  pour cut-out: 3065.36,-3195 3133,-3195 3133,-3282 3065.36,-3282
  pour cut-out: 2946.04,-2121.73 2946.04,-2181.28 2866.81,-2181.28 2866.81,-2121.73
  region net GND: 2679.54,-3584.74 2693.29,-3590.44 2705.67,-3598.71 2716.2,-3609.23 2724.47,-3621.61 2730.17,-3635.37 2733.07,-3649.97 2733.07,-3657.42 2733.07,-3664.17 2730.44,-3677.42 2725.27,-3689.9 2717.76,-3701.14 2708.21,-3710.69 2696.97,-3718.19 2684.49,-3723.36 2671.24,-3726 2387.87,-3726 2373.35,-3723.11 2359.67,-3717.45 2347.37,-3709.22 2336.9,-3698.76 2328.68,-3686.45 2323.01,-3672.77 2320.12,-3658.26 2320.12,-3650.85 2320.12,-3644.06 2322.78,-3630.72 2327.98,-3618.16 2335.53,-3606.86 2345.15,-3597.24 2356.45,-3589.69 2369.01,-3584.49 2382.35,-3581.83 2664.93,-3581.83 hole: 2622.61,-3616 2612.81,-3617.29 2603.67,-3621.07 2595.83,-3627.09 2589.81,-3634.94 2586.02,-3644.08 2584.73,-3653.88 2586.02,-3663.69 2589.81,-3672.82 2595.83,-3680.67 2603.67,-3686.69 2612.81,-3690.47 2622.61,-3691.76 2632.42,-3690.47 2641.56,-3686.69 2649.4,-3680.67 2655.42,-3672.82 2659.21,-3663.69 2660.5,-3653.88 2659.21,-3644.08 2655.42,-3634.94 2649.4,-3627.09 2641.56,-3621.07 2632.42,-3617.29 hole: 2430.49,-3616 2420.68,-3617.29 2411.55,-3621.07 2403.7,-3627.09 2397.68,-3634.94 2393.9,-3644.08 2392.61,-3653.88 2393.9,-3663.69 2397.68,-3672.82 2403.7,-3680.67 2411.55,-3686.69 2420.68,-3690.47 2430.49,-3691.76 2440.29,-3690.47 2449.43,-3686.69 2457.28,-3680.67 2463.3,-3672.82 2467.08,-3663.69 2468.37,-3653.88 2467.08,-3644.08 2463.3,-3634.94 2457.28,-3627.09 2449.43,-3621.07 2440.29,-3617.29
  region net GND: 2410,-2945 2410,-3166.65 2630.04,-3166.65 2630.04,-2946.17
  pour cut-out: 2600,-465 2761.22,-465 2761.22,-555.96 2600,-555.96
  pour cut-out: 2551.06,-689.84 2610.61,-689.84 2610.61,-769.08 2551.06,-769.08
  pour cut-out: 2217.99,-689.84 2277.54,-689.84 2277.54,-769.08 2217.99,-769.08
  pour cut-out: 2117.99,-689.84 2177.54,-689.84 2177.54,-769.08 2117.99,-769.08
  pour cut-out: 2905,-2010
  pour cut-out: 2905,-2010
  pour cut-out: 2384.57,-2921.17 2655.04,-2921.17 2655.04,-3191.65 2384.57,-3191.65
  pour cut-out: 1874.32,-3535.52 2061.4,-3535.52 2061.4,-3638.35 1874.32,-3638.35
  pour cut-out: 2061.4,-2487.85 2061.4,-2590.68 1880,-2590.68 1880,-2487.85
  pour cut-out: 1603.36,-2609.46 1688.36,-2609.46 1688.36,-2779.46 1603.36,-2779.46
  pour cut-out: 1603.36,-2965 1688.36,-2965 1688.36,-3135 1603.36,-3135
  pour cut-out: 1688.36,-3306.74 1603.36,-3306.74 1603.36,-3476.74 1688.36,-3476.74
  pour cut-out: 2061.4,-3287.96 2061.4,-3185.13 1880,-3185.13 1880,-3287.96
  pour cut-out: 2178,-3146.21 2178,-2921.21 2183.97,-2921.21 2183.97,-2906.79 2263.39,-2906.79 2263.39,-3146.21
  pour cut-out: 2855,-3191.61 2861.6,-3191.61 2861.6,-2966.61 2776.21,-2966.61 2776.21,-3206.03 2855,-3206.03
  pour cut-out: 2384.57,-2921.17
  region net BAT-VSEN: 785,-1217.5 794.5,-1227 905,-1227 952,-1180 1127.5,-1180 1140,-1167.5 1140,-647.99 1117.01,-625 853.72,-625 785,-693.72 785,-945 759.51,-970.49 759.51,-1102.45 785,-1127.94
  region net P12V-BAT: 290,-1020.32 385.86,-924.46 385.86,-587.32 419.18,-554 717.06,-554 759.51,-596.45 759.51,-921.63 732.5,-948.64 732.5,-1099.36 708.42,-1123.45 605.99,-1123.45 561.41,-1168.02 561.41,-1225.78 530.56,-1256.62 331.95,-1256.62 290,-1214.67
  pour cut-out: 880,-1708 1100,-1708 1320,-1708 1320,-2240 690,-2240 690,-1708
  pour cut-out: 777.2,-1478.72 777.2,-1130 1165.49,-1130 1165.49,-1478.72
  region net P5V-Main: 1100,-2050 1120,-2070 1200,-2070 1320,-2070 1360,-2030 1360,-1950 1390,-1920 1430,-1920 1580,-1920 1610,-1890 1832.96,-1890 1842.96,-1880 1842.96,-1780 1832.96,-1770 1157.5,-1770 1100,-1827.5 1100,-1849.46
  region net NetD2_1: 957,-1205 1126,-1205 1133.75,-1212.75 1133.75,-1240.25 1127,-1247 988,-1247 926,-1309 926,-1662 880,-1708 880,-2040 865,-2055 715,-2055 690,-2030 690,-1659.45 775,-1574.45 775,-1266.25 794.25,-1247 915,-1247
  region: 0,0
  region: 982.01,-2783.89
  pour cut-out: 3920.54,-2469.05
  pour cut-out: 3920.54,-2469.05
  region: 310.86,-999.46
Bottom Layer:
  region net EARTH: 15,-3875 3875,-3875.18 3875,-14.96 2890,-15 2890,-35 3855,-35 3855,-3855 35,-3855 35,-35 2480,-35 2480,-15 15,-15
  pour cut-out: 3199.29,-3443.05 3327.72,-3443.05 3327.72,-3590.22 3198.31,-3590.22
  pour cut-out: 550.32,-1821.3 550.32,-1940 615.98,-1940 615.98,-1821.3
  pour cut-out: 2621.61,-3278.14 2621.61,-3412.51 2791.4,-3412.51 2791.4,-3278.14
  pour cut-out: 2024,-2921.21 2152.43,-2921.21 2152.43,-3180.9 2024,-3180.9
  pour cut-out: 2971.74,-2175.06 3029.61,-2175.06 3029.61,-2032.36 2971.74,-2032.36
  pour cut-out: 650,-2390 923.39,-2390 923.39,-2624.07 1460,-2624.07 1460,-2770 935,-2770 935,-3334.07 1460,-3334.07 1460,-3480 935,-3480 935,-3855 35,-3855 35,-2480 650,-2480
  pour cut-out: 2730.38,-3076.29 2545.32,-3076.29 2545.32,-2931.92 2730.38,-2931.92
  pour cut-out: 2689.68,-2712.38 2689.68,-2540.41 2395.32,-2540.41 2395.32,-2712.38
  pour cut-out: 2358.52,-2570.57 2269.7,-2570.57 2269.7,-2509.12 2358.52,-2509.12
  pour cut-out: 2052.54,-2775.7 1982.54,-2775.7 1982.54,-2647.27 2052.54,-2647.27
  pour cut-out: 1830.79,-2735 1830.79,-2780.03 1777.33,-2780.03 1777.33,-2708 1830.79,-2708
  pour cut-out: 3200.39,-3008.91 3327.72,-3008.91 3327.72,-2869 3200.39,-2869
  pour cut-out: 2045,-2350 2045,-2399.83 1989.67,-2399.83 1989.67,-2327.8 2045,-2327.8
  pour cut-out: 1830.79,-3400.07 1830.79,-3477.31 1777.33,-3477.31 1777.33,-3400.07
  pour cut-out: 2052.54,-3344.55 2052.54,-3472.98 1982.54,-3472.98 1982.54,-3344.55
  pour cut-out: 3324.51,-2195.85 3324.51,-2350.22 3150.39,-2350.22 3150.39,-2195.85
  pour cut-out: 3327.72,-1840.85 3327.72,-1990.22 3150.39,-1990.22 3150.39,-1840.85
  pour cut-out: 2564.29,-3411.52 2267.62,-3411.52 2267.62,-3286.13 2564.29,-3286.13
  region net CLOSE1: 675,-2900 725,-2850 887.6,-2850 900,-2862.4 900,-3000 890,-3010 59,-3010 46.49,-2997.49 46.49,-2910 56.49,-2900
  region net OPEN1: 58,-2480 550,-2480 640,-2390 890,-2390 900,-2400 900,-2530 890,-2540 650,-2540 570,-2620 58,-2620 47,-2609 47,-2491
  region net COM1: 55.75,-2700 603.57,-2700 679.51,-2624.07 1440.87,-2624.07 1460,-2643.2 1460,-2756.46 1446.46,-2770 688.57,-2770 638.57,-2820 60,-2820 45,-2805 45,-2710.75
  region net COM2: 55.75,-3410 603.57,-3410 679.51,-3334.07 1440.87,-3334.07 1460,-3353.2 1460,-3466.46 1446.46,-3480 688.57,-3480 638.57,-3530 60,-3530 45,-3515 45,-3420.75
  region net OPEN2: 58,-3190 550,-3190 650,-3090 890,-3090 900,-3100 900,-3240 890,-3250 650,-3250 570,-3330 58,-3330 47,-3319 47,-3201
  region net CLOSE2: 675,-3610 725,-3560 887.6,-3560 900,-3572.4 900,-3710 890,-3720 59,-3720 46.49,-3707.49 46.49,-3620 56.49,-3610
Multi-Layer:
  pour cut-out: 2480,-35 35,-35 35,-3855 3855,-3855 3855,-35 2890,-35 2890,-60.49 3829.51,-60.49 3829.51,-3829.51 60.49,-3829.51 60.49,-60.49 2480,-60.49
  pour cut-out: 1850.99,-35 2000,-35 2000,-1115 3025,-1115 3025,-1215 1850.99,-1215
  pour cut-out: 1900,-1215 1850,-1215 1850,-1744.51 2000,-1744.51 2000,-1215
  pour cut-out: 35,-1640 690,-1640 690,-2240 1466.2,-2240 1466.2,-2290 615.98,-2290 615.98,-1690 35,-1690
  pour cut-out: 3855,-1580 3855,-1650 3200,-1650 3200,-1215 3025,-1215 3025,-35 3125,-35 3125,-1115 3300,-1115 3300,-1580

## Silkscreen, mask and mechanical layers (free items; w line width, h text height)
Top Overlay:
  drawing of 802 lines, arcs and shapes, not listed
  text "-" at 453.14,-188.99 h393.7
  text "-" at 3209.05,-188.99 h393.7
  text "SENSOR NODE / V3.1" at 1830,-273 h47.24
  text "FEMALE" at 765,-350 h70.87 r270
  text "FEMALE" at 3112.5,-765 h70.87 r90
  text "+BAT" at 310,-960 h120
  text "+SOLAR" at 3442.39,-970 h118.11
  text "+" at 614.07,-1161.66 h196.85 r90
  text "+" at 3380.32,-1175 h196.85 r90
  text "-" at 3365,-1500 h275.59 r90
  text "-" at 614.07,-1565.77 h275.59 r90
  text "-" at 455,-1720 h275.59 r90
Bottom Overlay:
  drawing of 806 lines, arcs and shapes, not listed
  text "SN:" at 2940,-990 h60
